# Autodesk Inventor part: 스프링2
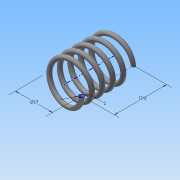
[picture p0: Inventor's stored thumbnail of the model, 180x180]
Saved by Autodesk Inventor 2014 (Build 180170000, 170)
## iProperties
Created: 2016-01
Part Number: 스프링2
Material: 강철, 탄소
Document SubType Name: Modeling
Designer: Administrator
Density: 1 g/cm^3
Appearance: 반연마
Mass: 0.818602 g
Surface Area: 16.6857 cm^2
Volume: 0.818602 cm^3
Author: Administrator
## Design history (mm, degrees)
sketch "스케치1"
  geometry: L1 (0, 0)-(8.5, 0); L2 (8.5, 0)-(8.5, 17.5); L3 (8.5, 17.5)-(0, 17.5); L4 (0, 17.5)-(0, 0); C1 r 1 at (8.5, 0)
  constraints: 8 end point, 2 parallel, 1 centre point, 1 coincident, 1 horizontal, 1 perpendicular
  dimensions: "d0" = 17 diameter of L2 L4; "d1" = 17.5 distance of L1.end L2.end (derived); "d2" = 2 diameter of C1
feature "코일1" pitch "d3" = 10; turns "d5" = 5; dims "d4" = 17.5 (= d1), "d6" = 0, angle "d7" = 90 deg, angle "d8" = 90 deg, "d9" = 0, "d10" = 0
node "작업 평면1"
sketch "스케치2"
  geometry: L1 (-9.5, 0)-(-7.5, 0) reference; 1 further point
  constraints: 1 horizontal alignment
extrude "돌출1" cut sketch "스케치2" distance "d12" = 10; taper "d13" = 0 deg
node "작업 평면2"
sketch "스케치3"
  geometry: L1 (-7.5, 0)-(-9.5, 0) reference; 1 further point
  constraints: 1 horizontal alignment
extrude "돌출2" cut sketch "스케치3" distance "d15" = 10; taper "d16" = 0 deg
node "솔리드1"
node "절단 모서리 투영1"
node "절단 모서리 투영2"
other parameters: "d11" = 0, "d14" = 17.5 (= d1)
